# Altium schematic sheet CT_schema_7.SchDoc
size 278 x 170 mm
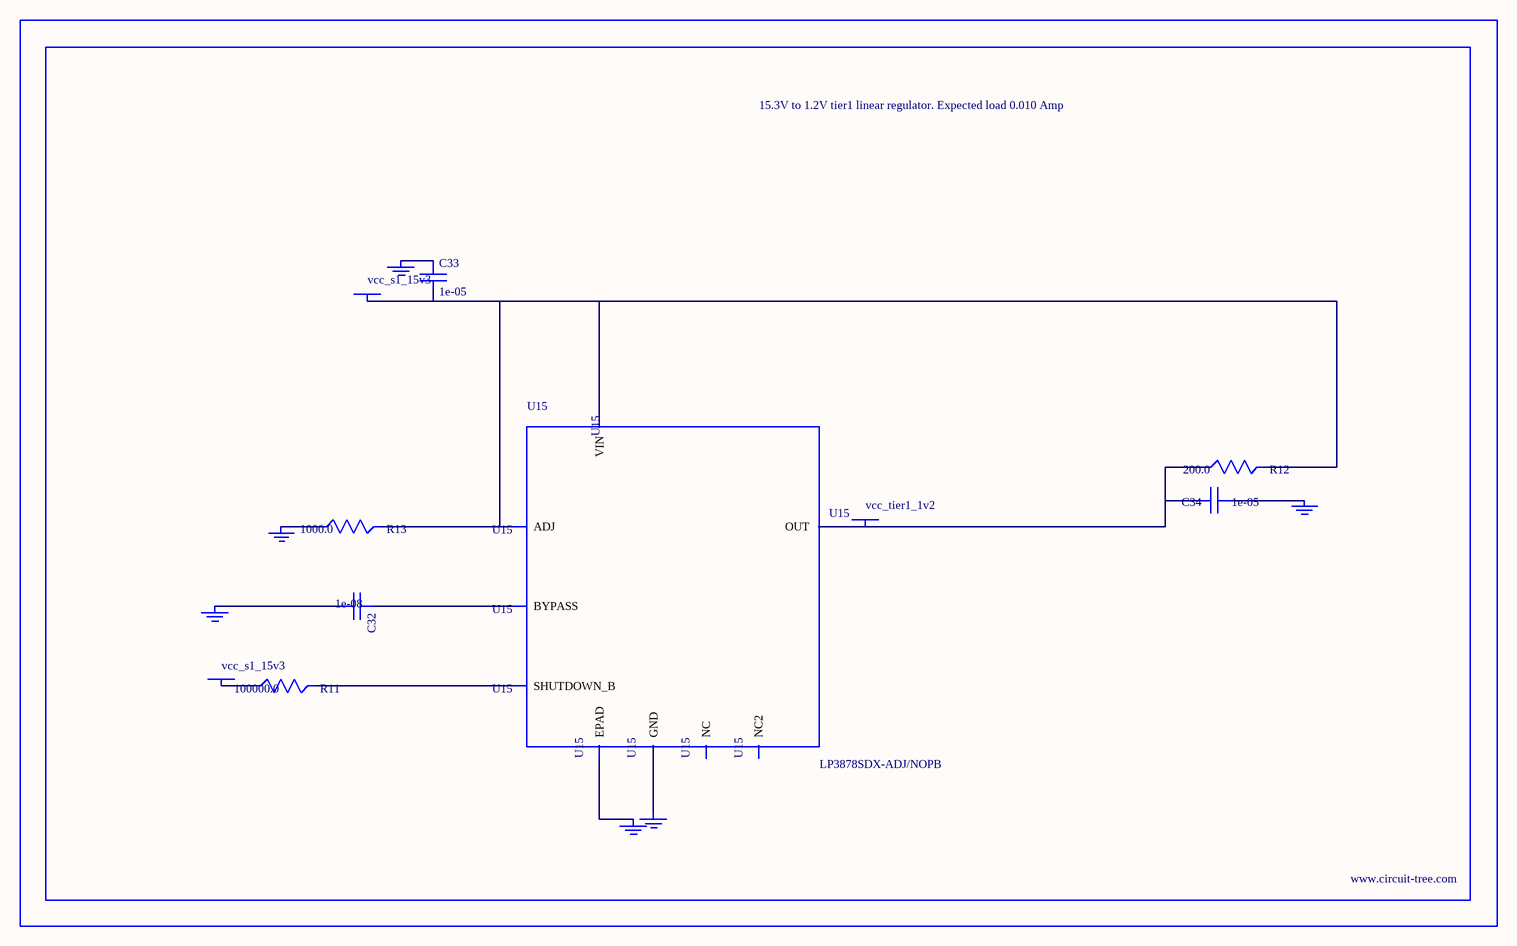
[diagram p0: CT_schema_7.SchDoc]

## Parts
BORDER6  (no value)
C32  1e-08  [C0402]
C33  1e-05  [C1210]
C34  1e-05  [C0805]
GND_INSTANCE_6_0  (no value)
GND_INSTANCE_6_1  (no value)
GND_INSTANCE_6_2  (no value)
GND_INSTANCE_6_3  (no value)
GND_INSTANCE_6_4  (no value)
GND_INSTANCE_6_5  (no value)
POWER_INSTANCE_6_0  vcc_s1_15v3
POWER_INSTANCE_6_1  vcc_s1_15v3
POWER_INSTANCE_6_2  vcc_tier1_1v2
R11  100000.0  [R0603]
R12  200.0  [R0603]
R13  1000.0  [R0603]
U15  LP3878SDX-ADJ/NOPB  [WSON-8]

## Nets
NetC32_1: C32.1 U15.1(BYPASS)
NetC32_2: C32.2 GND_INSTANCE_6_0.0(GND)
NetC33_1: C33.1 GND_INSTANCE_6_1.0(GND)
NetC33_2: C33.2 POWER_INSTANCE_6_0.0(PWR) R12.2 R13.2 U15.4(VIN) U15.6(ADJ)
NetC34_1: C34.1 GND_INSTANCE_6_2.0(GND)
NetC34_2: C34.2 POWER_INSTANCE_6_2.0(PWR) R12.1 U15.5(OUT)
NetGND_INSTANCE_6_3_0: GND_INSTANCE_6_3.0(GND) R13.1
NetGND_INSTANCE_6_4_0: GND_INSTANCE_6_4.0(GND) U15.PAD(EPAD)
NetGND_INSTANCE_6_5_0: GND_INSTANCE_6_5.0(GND) U15.3(GND)
NetPOWER_INSTANCE_6_1_0: POWER_INSTANCE_6_1.0(PWR) R11.1
NetR11_2: R11.2 U15.8(SHUTDOWN_B)

Not connected (* = marked no-connect by the designer): U15 2(NC) 7(NC2)

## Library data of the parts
BORDER6 = BORDER_PAGE6
C32 = C0402C103K3RAC
C33 = C1210C106K5PACTU
C34 = GRM219R60J106ME19D
GND_INSTANCE_6_0-GND_INSTANCE_6_5 = GND
POWER_INSTANCE_6_0-POWER_INSTANCE_6_2 = PWR
R11 = RC0603JR-07100KL
R12 = RC0603JR-07200RL
R13 = RC0603JR-071KL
